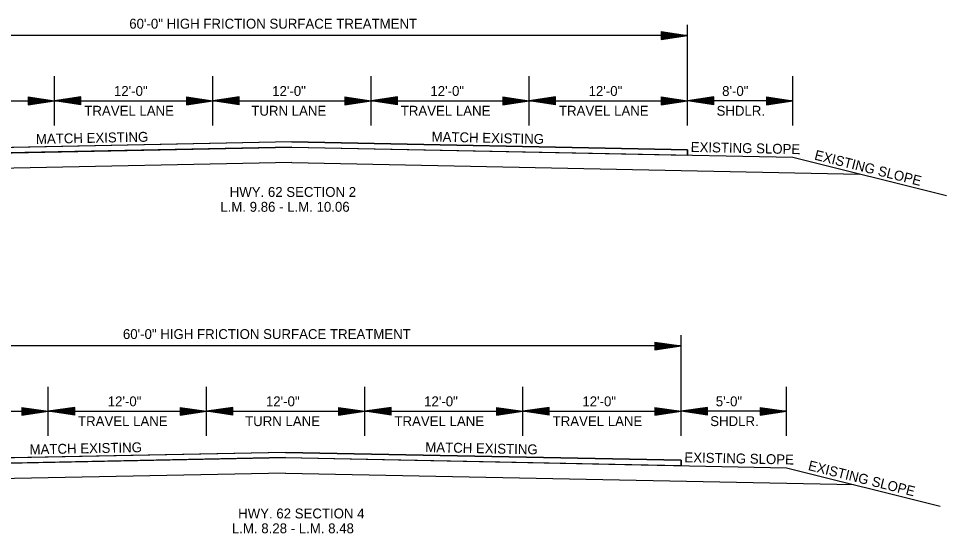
# Model space of a CAD drawing. Extents: x 34757 to 38214, y 51436 to 59430.
# Drawn here: x 37158 to 38214, y 53659 to 54244 of the extents above; entities that cross this region are included whole.
import ezdxf

# ---------------------------------------------------------------- set-up
doc = ezdxf.new("R2010")
doc.units = 0
for name, color, linetype in [('Default', 7, 'Continuous'), ('R_Border', 7, 'Continuous'), ('R_Draft', 7, 'Continuous')]:
    doc.layers.add(name, color=color, linetype=linetype)

msp = doc.modelspace()

# ---------------------------------------------------------------- linework, layer by layer
at = {"layer": 'Default'}
for p, q in [((37919.2, 54122.4), (37919.2, 54236.8)), ((37919.2, 54224.7), (37019.2, 54224.6)), ((37889.2, 54229.2), (37919.2, 54224.7)), ((37889.2, 54229.2), (37889.2, 54220.2)), ((37889.2, 54228.4), (37914.2, 54224.7)), ((37889.2, 54227.7), (37909, 54224.7)), ((37889.2, 54226.9), (37904, 54224.7)), ((37889.2, 54226.1), (37899, 54224.7)), ((37889.2, 54225.4), (37893.9, 54224.7)), ((37889.2, 54220.2), (37919.2, 54224.7)), ((37889.2, 54223.2), (37899, 54224.7)), ((37889.2, 54221.7), (37909, 54224.7)), ((37889.2, 54220.9), (37914.2, 54224.7)), ((37889.2, 54222.4), (37904, 54224.7)), ((37889.2, 54224), (37893.9, 54224.7)), ((37199.2, 54122.4), (37199.2, 54178.4)), ((37379.2, 54122.4), (37379.2, 54178.4)), ((37559.2, 54122.4), (37559.2, 54178.4)), ((37739.2, 54122.4), (37739.2, 54178.4)), ((37919.2, 54122.4), (37919.2, 54178.4)), ((38039.2, 54122.4), (38039.2, 54178.4)), ((37019.2, 54150.4), (37199.2, 54150.4)), ((37169.2, 54154.9), (37199.2, 54150.4)), ((37169.2, 54154.9), (37169.2, 54145.9)), ((37169.2, 54154.1), (37194.2, 54150.4)), ((37169.2, 54153.4), (37189, 54150.4)), ((37169.2, 54152.6), (37184, 54150.4)), ((37169.2, 54151.8), (37179, 54150.4)), ((37169.2, 54151.1), (37173.9, 54150.4)), ((37169.2, 54145.9), (37199.2, 54150.4)), ((37169.2, 54148.9), (37179, 54150.4)), ((37169.2, 54147.4), (37189, 54150.4)), ((37169.2, 54146.6), (37194.2, 54150.4)), ((37169.2, 54148.2), (37184, 54150.4)), ((37169.2, 54149.7), (37173.9, 54150.4)), ((37229.2, 54154.9), (37199.2, 54150.4)), ((37199.2, 54150.4), (37379.2, 54150.4)), ((37229.2, 54145.9), (37199.2, 54150.4)), ((37229.2, 54154.1), (37204.2, 54150.4)), ((37229.2, 54146.6), (37204.2, 54150.4)), ((37229.2, 54153.4), (37209.4, 54150.4)), ((37229.2, 54147.4), (37209.4, 54150.4)), ((37229.2, 54152.6), (37214.4, 54150.4)), ((37229.2, 54148.2), (37214.4, 54150.4)), ((37229.2, 54151.9), (37219.5, 54150.4)), ((37229.2, 54148.9), (37219.5, 54150.4)), ((37229.2, 54151.1), (37224.5, 54150.4)), ((37229.2, 54149.7), (37224.5, 54150.4)), ((37229.2, 54145.9), (37229.2, 54154.9)), ((37349.2, 54154.9), (37379.2, 54150.4)), ((37349.2, 54154.9), (37349.2, 54145.9)), ((37349.2, 54154.1), (37374.2, 54150.4)), ((37349.2, 54153.4), (37369, 54150.4)), ((37349.2, 54152.6), (37364, 54150.4)), ((37349.2, 54151.8), (37359, 54150.4)), ((37349.2, 54151.1), (37353.9, 54150.4)), ((37349.2, 54145.9), (37379.2, 54150.4)), ((37349.2, 54148.9), (37359, 54150.4)), ((37349.2, 54147.4), (37369, 54150.4)), ((37349.2, 54146.6), (37374.2, 54150.4)), ((37349.2, 54148.2), (37364, 54150.4)), ((37349.2, 54149.7), (37353.9, 54150.4)), ((37409.2, 54154.9), (37379.2, 54150.4)), ((37379.2, 54150.4), (37559.2, 54150.4)), ((37409.2, 54145.9), (37379.2, 54150.4)), ((37409.2, 54154.1), (37384.2, 54150.4)), ((37409.2, 54146.6), (37384.2, 54150.4)), ((37409.2, 54153.4), (37389.4, 54150.4)), ((37409.2, 54147.4), (37389.4, 54150.4)), ((37409.2, 54152.6), (37394.4, 54150.4)), ((37409.2, 54148.2), (37394.4, 54150.4)), ((37409.2, 54151.9), (37399.5, 54150.4)), ((37409.2, 54148.9), (37399.5, 54150.4)), ((37409.2, 54151.1), (37404.5, 54150.4)), ((37409.2, 54149.7), (37404.5, 54150.4)), ((37409.2, 54145.9), (37409.2, 54154.9)), ((37529.2, 54154.9), (37559.2, 54150.4)), ((37529.2, 54154.9), (37529.2, 54145.9)), ((37529.2, 54154.1), (37554.2, 54150.4)), ((37529.2, 54153.4), (37549, 54150.4)), ((37529.2, 54152.6), (37544, 54150.4)), ((37529.2, 54151.8), (37539, 54150.4)), ((37529.2, 54151.1), (37533.9, 54150.4)), ((37529.2, 54145.9), (37559.2, 54150.4)), ((37529.2, 54148.9), (37539, 54150.4)), ((37529.2, 54147.4), (37549, 54150.4)), ((37529.2, 54146.6), (37554.2, 54150.4)), ((37529.2, 54148.2), (37544, 54150.4)), ((37529.2, 54149.7), (37533.9, 54150.4)), ((37589.2, 54154.9), (37559.2, 54150.4)), ((37559.2, 54150.4), (37739.2, 54150.4)), ((37589.2, 54145.9), (37559.2, 54150.4)), ((37589.2, 54154.1), (37564.2, 54150.4)), ((37589.2, 54146.6), (37564.2, 54150.4)), ((37589.2, 54153.4), (37569.4, 54150.4)), ((37589.2, 54147.4), (37569.4, 54150.4)), ((37589.2, 54152.6), (37574.4, 54150.4)), ((37589.2, 54148.2), (37574.4, 54150.4)), ((37589.2, 54151.9), (37579.5, 54150.4)), ((37589.2, 54148.9), (37579.5, 54150.4)), ((37589.2, 54151.1), (37584.5, 54150.4)), ((37589.2, 54149.7), (37584.5, 54150.4)), ((37589.2, 54145.9), (37589.2, 54154.9)), ((37709.2, 54154.9), (37739.2, 54150.4)), ((37709.2, 54154.9), (37709.2, 54145.9)), ((37709.2, 54154.1), (37734.2, 54150.4)), ((37709.2, 54153.4), (37729, 54150.4)), ((37709.2, 54152.6), (37724, 54150.4)), ((37709.2, 54151.8), (37719, 54150.4)), ((37709.2, 54151.1), (37713.9, 54150.4)), ((37709.2, 54145.9), (37739.2, 54150.4)), ((37709.2, 54148.9), (37719, 54150.4)), ((37709.2, 54147.4), (37729, 54150.4)), ((37709.2, 54146.6), (37734.2, 54150.4)), ((37709.2, 54148.2), (37724, 54150.4)), ((37709.2, 54149.7), (37713.9, 54150.4)), ((37769.2, 54154.9), (37739.2, 54150.4)), ((37739.2, 54150.4), (37919.2, 54150.4)), ((37769.2, 54145.9), (37739.2, 54150.4)), ((37769.2, 54154.1), (37744.2, 54150.4)), ((37769.2, 54146.6), (37744.2, 54150.4)), ((37769.2, 54153.4), (37749.4, 54150.4)), ((37769.2, 54147.4), (37749.4, 54150.4)), ((37769.2, 54152.6), (37754.4, 54150.4)), ((37769.2, 54148.2), (37754.4, 54150.4)), ((37769.2, 54151.9), (37759.5, 54150.4)), ((37769.2, 54148.9), (37759.5, 54150.4)), ((37769.2, 54151.1), (37764.5, 54150.4)), ((37769.2, 54149.7), (37764.5, 54150.4)), ((37769.2, 54145.9), (37769.2, 54154.9)), ((37889.2, 54154.9), (37919.2, 54150.4)), ((37889.2, 54154.9), (37889.2, 54145.9)), ((37889.2, 54154.1), (37914.2, 54150.4)), ((37889.2, 54153.4), (37909, 54150.4)), ((37889.2, 54152.6), (37904, 54150.4)), ((37889.2, 54151.8), (37899, 54150.4)), ((37889.2, 54151.1), (37893.9, 54150.4)), ((37889.2, 54145.9), (37919.2, 54150.4)), ((37889.2, 54148.9), (37899, 54150.4)), ((37889.2, 54147.4), (37909, 54150.4)), ((37889.2, 54146.6), (37914.2, 54150.4)), ((37889.2, 54148.2), (37904, 54150.4)), ((37889.2, 54149.7), (37893.9, 54150.4)), ((37949.2, 54154.9), (37919.2, 54150.4)), ((38039.2, 54150.4), (37919.2, 54150.4)), ((37949.2, 54145.9), (37919.2, 54150.4)), ((37949.2, 54154.1), (37924.2, 54150.4)), ((37949.2, 54146.6), (37924.2, 54150.4)), ((37949.2, 54153.4), (37929.4, 54150.4)), ((37949.2, 54147.4), (37929.4, 54150.4)), ((37949.2, 54152.6), (37934.4, 54150.4)), ((37949.2, 54148.2), (37934.4, 54150.4)), ((37949.2, 54151.9), (37939.5, 54150.4)), ((37949.2, 54148.9), (37939.5, 54150.4)), ((37949.2, 54151.1), (37944.5, 54150.4)), ((37949.2, 54149.7), (37944.5, 54150.4)), ((37949.2, 54145.9), (37949.2, 54154.9)), ((38009.2, 54154.9), (38039.2, 54150.4)), ((38009.2, 54154.9), (38009.2, 54145.9)), ((38009.2, 54154.1), (38034.2, 54150.4)), ((38009.2, 54153.4), (38029, 54150.4)), ((38009.2, 54152.6), (38024, 54150.4)), ((38009.2, 54151.8), (38019, 54150.4)), ((38009.2, 54151.1), (38013.9, 54150.4)), ((38009.2, 54145.9), (38039.2, 54150.4)), ((38009.2, 54148.9), (38019, 54150.4)), ((38009.2, 54147.4), (38029, 54150.4)), ((38009.2, 54146.6), (38034.2, 54150.4)), ((38009.2, 54148.2), (38024, 54150.4)), ((38009.2, 54149.7), (38013.9, 54150.4)), ((37469.2, 54103.7), (37019.2, 54094.7)), ((37469.2, 54103.7), (37919.2, 54094.7)), ((38039.2, 54086.3), (38213.8, 54042.6)), ((37469.2, 54080.2), (36823.1, 54067.2)), ((37469.2, 54080.2), (38115.3, 54067.2)), ((37912, 53769.5), (37912, 53883.9)), ((37912, 53871.7), (37012, 53871.7)), ((37882, 53876.2), (37912, 53871.7)), ((37882, 53876.2), (37882, 53867.2)), ((37882, 53875.5), (37907, 53871.7)), ((37882, 53874.7), (37901.8, 53871.7)), ((37882, 53874), (37896.9, 53871.7)), ((37882, 53873.2), (37891.8, 53871.7)), ((37882, 53872.4), (37886.8, 53871.7)), ((37882, 53867.2), (37912, 53871.7)), ((37882, 53870.2), (37891.8, 53871.7)), ((37882, 53868.7), (37901.8, 53871.7)), ((37882, 53868), (37907, 53871.7)), ((37882, 53869.5), (37896.9, 53871.7)), ((37882, 53871), (37886.8, 53871.7)), ((37192, 53769.5), (37192, 53825.4)), ((37372, 53769.5), (37372, 53825.4)), ((37552, 53769.5), (37552, 53825.4)), ((37732, 53769.5), (37732, 53825.4)), ((37912, 53769.5), (37912, 53825.4)), ((38032, 53769.5), (38032, 53825.4)), ((37012, 53797.4), (37192, 53797.4)), ((37162, 53801.9), (37192, 53797.4)), ((37162, 53801.9), (37162, 53792.9)), ((37162, 53801.2), (37187, 53797.4)), ((37162, 53800.4), (37181.8, 53797.4)), ((37162, 53799.7), (37176.9, 53797.4)), ((37162, 53798.9), (37171.8, 53797.4)), ((37162, 53798.1), (37166.8, 53797.4)), ((37162, 53792.9), (37192, 53797.4)), ((37162, 53796), (37171.8, 53797.4)), ((37162, 53794.5), (37181.8, 53797.4)), ((37162, 53793.7), (37187, 53797.4)), ((37162, 53795.2), (37176.9, 53797.4)), ((37162, 53796.7), (37166.8, 53797.4)), ((37222, 53801.9), (37192, 53797.4)), ((37192, 53797.4), (37372, 53797.4)), ((37222, 53792.9), (37192, 53797.4)), ((37222, 53801.2), (37197, 53797.4)), ((37222, 53793.7), (37197, 53797.4)), ((37222, 53800.4), (37202.2, 53797.4)), ((37222, 53794.5), (37202.2, 53797.4)), ((37222, 53799.7), (37207.2, 53797.4)), ((37222, 53795.2), (37207.2, 53797.4)), ((37222, 53798.9), (37212.3, 53797.4)), ((37222, 53796), (37212.3, 53797.4)), ((37222, 53798.1), (37217.3, 53797.4)), ((37222, 53796.7), (37217.3, 53797.4)), ((37222, 53792.9), (37222, 53801.9)), ((37342, 53801.9), (37372, 53797.4)), ((37342, 53801.9), (37342, 53792.9)), ((37342, 53801.2), (37367, 53797.4)), ((37342, 53800.4), (37361.8, 53797.4)), ((37342, 53799.7), (37356.9, 53797.4)), ((37342, 53798.9), (37351.8, 53797.4)), ((37342, 53798.1), (37346.8, 53797.4)), ((37342, 53792.9), (37372, 53797.4)), ((37342, 53796), (37351.8, 53797.4)), ((37342, 53794.5), (37361.8, 53797.4)), ((37342, 53793.7), (37367, 53797.4)), ((37342, 53795.2), (37356.9, 53797.4)), ((37342, 53796.7), (37346.8, 53797.4)), ((37402, 53801.9), (37372, 53797.4)), ((37372, 53797.4), (37552, 53797.4)), ((37402, 53792.9), (37372, 53797.4)), ((37402, 53801.2), (37377, 53797.4)), ((37402, 53793.7), (37377, 53797.4)), ((37402, 53800.4), (37382.2, 53797.4)), ((37402, 53794.5), (37382.2, 53797.4)), ((37402, 53799.7), (37387.2, 53797.4)), ((37402, 53795.2), (37387.2, 53797.4)), ((37402, 53798.9), (37392.3, 53797.4)), ((37402, 53796), (37392.3, 53797.4)), ((37402, 53798.1), (37397.3, 53797.4)), ((37402, 53796.7), (37397.3, 53797.4)), ((37402, 53792.9), (37402, 53801.9)), ((37522, 53801.9), (37552, 53797.4)), ((37522, 53801.9), (37522, 53792.9)), ((37522, 53801.2), (37547, 53797.4)), ((37522, 53800.4), (37541.8, 53797.4)), ((37522, 53799.7), (37536.9, 53797.4)), ((37522, 53798.9), (37531.8, 53797.4)), ((37522, 53798.1), (37526.8, 53797.4)), ((37522, 53792.9), (37552, 53797.4)), ((37522, 53796), (37531.8, 53797.4)), ((37522, 53794.5), (37541.8, 53797.4)), ((37522, 53793.7), (37547, 53797.4)), ((37522, 53795.2), (37536.9, 53797.4)), ((37522, 53796.7), (37526.8, 53797.4)), ((37582, 53801.9), (37552, 53797.4)), ((37552, 53797.4), (37732, 53797.4)), ((37582, 53792.9), (37552, 53797.4)), ((37582, 53801.2), (37557, 53797.4)), ((37582, 53793.7), (37557, 53797.4)), ((37582, 53800.4), (37562.2, 53797.4)), ((37582, 53794.5), (37562.2, 53797.4)), ((37582, 53799.7), (37567.2, 53797.4)), ((37582, 53795.2), (37567.2, 53797.4)), ((37582, 53798.9), (37572.3, 53797.4)), ((37582, 53796), (37572.3, 53797.4)), ((37582, 53798.1), (37577.3, 53797.4)), ((37582, 53796.7), (37577.3, 53797.4)), ((37582, 53792.9), (37582, 53801.9)), ((37702, 53801.9), (37732, 53797.4)), ((37702, 53801.9), (37702, 53792.9)), ((37702, 53801.2), (37727, 53797.4)), ((37702, 53800.4), (37721.8, 53797.4)), ((37702, 53799.7), (37716.9, 53797.4)), ((37702, 53798.9), (37711.8, 53797.4)), ((37702, 53798.1), (37706.8, 53797.4)), ((37702, 53792.9), (37732, 53797.4)), ((37702, 53796), (37711.8, 53797.4)), ((37702, 53794.5), (37721.8, 53797.4)), ((37702, 53793.7), (37727, 53797.4)), ((37702, 53795.2), (37716.9, 53797.4)), ((37702, 53796.7), (37706.8, 53797.4)), ((37762, 53801.9), (37732, 53797.4)), ((37732, 53797.4), (37912, 53797.4)), ((37762, 53792.9), (37732, 53797.4)), ((37762, 53801.2), (37737, 53797.4)), ((37762, 53793.7), (37737, 53797.4)), ((37762, 53800.4), (37742.2, 53797.4)), ((37762, 53794.5), (37742.2, 53797.4)), ((37762, 53799.7), (37747.2, 53797.4)), ((37762, 53795.2), (37747.2, 53797.4)), ((37762, 53798.9), (37752.3, 53797.4)), ((37762, 53796), (37752.3, 53797.4)), ((37762, 53798.1), (37757.3, 53797.4)), ((37762, 53796.7), (37757.3, 53797.4)), ((37762, 53792.9), (37762, 53801.9)), ((37882, 53801.9), (37912, 53797.4)), ((37882, 53801.9), (37882, 53792.9)), ((37882, 53801.2), (37907, 53797.4)), ((37882, 53800.4), (37901.8, 53797.4)), ((37882, 53799.7), (37896.9, 53797.4)), ((37882, 53798.9), (37891.8, 53797.4)), ((37882, 53798.1), (37886.8, 53797.4)), ((37882, 53792.9), (37912, 53797.4)), ((37882, 53796), (37891.8, 53797.4)), ((37882, 53794.5), (37901.8, 53797.4)), ((37882, 53793.7), (37907, 53797.4)), ((37882, 53795.2), (37896.9, 53797.4)), ((37882, 53796.7), (37886.8, 53797.4)), ((37942, 53801.9), (37912, 53797.4)), ((38032, 53797.4), (37912, 53797.4)), ((37942, 53792.9), (37912, 53797.4)), ((37942, 53801.2), (37917, 53797.4)), ((37942, 53793.7), (37917, 53797.4)), ((37942, 53800.4), (37922.2, 53797.4)), ((37942, 53794.5), (37922.2, 53797.4)), ((37942, 53799.7), (37927.2, 53797.4)), ((37942, 53795.2), (37927.2, 53797.4)), ((37942, 53798.9), (37932.3, 53797.4)), ((37942, 53796), (37932.3, 53797.4)), ((37942, 53798.1), (37937.3, 53797.4)), ((37942, 53796.7), (37937.3, 53797.4)), ((37942, 53792.9), (37942, 53801.9)), ((38002, 53801.9), (38032, 53797.4)), ((38002, 53801.9), (38002, 53792.9)), ((38002, 53801.2), (38027, 53797.4)), ((38002, 53800.4), (38021.8, 53797.4)), ((38002, 53799.7), (38016.9, 53797.4)), ((38002, 53798.9), (38011.8, 53797.4)), ((38002, 53798.1), (38006.8, 53797.4)), ((38002, 53792.9), (38032, 53797.4)), ((38002, 53796), (38011.8, 53797.4)), ((38002, 53794.5), (38021.8, 53797.4)), ((38002, 53793.7), (38027, 53797.4)), ((38002, 53795.2), (38016.9, 53797.4)), ((38002, 53796.7), (38006.8, 53797.4)), ((37462, 53750.7), (37012, 53741.7)), ((37462, 53750.7), (37912, 53741.7)), ((37462, 53727.2), (36815.9, 53714.3)), ((37462, 53727.2), (38108.1, 53714.3)), ((38032, 53733.3), (38206.6, 53689.6))]:
    msp.add_line(p, q, dxfattribs=at)
for points in [[(37019.2, 54094.7), (37019.2, 54088.7), (37469.2, 54097.7), (37919.2, 54088.7), (37919.2, 54094.7), (37469.2, 54103.7)], [(37012, 53741.7), (37012, 53735.7), (37462, 53744.7), (37912, 53735.7), (37912, 53741.7), (37462, 53750.7)]]:
    msp.add_lwpolyline(points, close=True, dxfattribs=at)
for points in [[(37469.2, 54097.7), (36899.2, 54086.3)], [(37469.2, 54097.7), (38039.2, 54086.3)], [(37462, 53744.7), (36892, 53733.3)], [(37462, 53744.7), (38032, 53733.3)]]:
    msp.add_lwpolyline(points, dxfattribs=at)
at = {"layer": 'R_Draft'}
for p, q in [((37919.2, 54094.7), (37919.2, 54088.7)), ((37912, 53741.7), (37912, 53735.7))]:
    msp.add_line(p, q, dxfattribs=at)

# ---------------------------------------------------------------- texts
at = {"layer": 'Default'}
for s, p in [('60\'-0" HIGH FRICTION SURFACE TREATMENT', (37284.1, 54232.5)), ('12\'-0"', (37266.7, 54156)), ('12\'-0"', (37446.7, 54156)), ('12\'-0"', (37626.7, 54156)), ('12\'-0"', (37806.7, 54156)), ('8\'-0"', (37958.6, 54156)), ('TRAVEL LANE', (37233, 54133.5)), ('TURN LANE', (37423, 54133.5)), ('TRAVEL LANE', (37593, 54133.5)), ('TRAVEL LANE', (37773, 54133.5)), ('SHDLR.', (37952.3, 54133.5)), ('60\'-0" HIGH FRICTION SURFACE TREATMENT', (37276.9, 53879.6)), ('12\'-0"', (37259.6, 53803.1)), ('12\'-0"', (37439.6, 53803.1)), ('12\'-0"', (37619.6, 53803.1)), ('12\'-0"', (37799.6, 53803.1)), ('5\'-0"', (37951.4, 53803.1)), ('TRAVEL LANE', (37225.8, 53780.6)), ('TURN LANE', (37415.9, 53780.6)), ('TRAVEL LANE', (37585.8, 53780.6)), ('TRAVEL LANE', (37765.8, 53780.6)), ('SHDLR.', (37945.1, 53780.6))]:
    msp.add_text(s, height=11.25, dxfattribs=at).set_placement(p)
for s, rotation, p in [('MATCH EXISTING', 1.146, (37178, 54101.4)), ('MATCH EXISTING', 358.7756, (37628, 54104.1)), ('EXISTING SLOPE', 358.7756, (37922.8, 54092.4)), ('EXISTING SLOPE', 345.9632, (38062.9, 54083.8)), ('MATCH EXISTING', 1.146, (37170.8, 53748.4)), ('MATCH EXISTING', 358.7756, (37620.8, 53751.1)), ('EXISTING SLOPE', 358.7756, (37915.6, 53739.5)), ('EXISTING SLOPE', 345.9632, (38055.7, 53730.8))]:
    msp.add_text(s, height=11.25, rotation=rotation, dxfattribs=at).set_placement(p)
at = {"layer": 'R_Border'}
for s, p in [('HWY. 62 SECTION 2', (37398.4, 54041.2)), ('L.M. 9.86 - L.M. 10.06', (37387.7, 54024.3)), ('HWY. 62 SECTION 4', (37408, 53675.6)), ('L.M. 8.28 - L.M. 8.48', (37400.9, 53658.7))]:
    msp.add_text(s, height=11.25, dxfattribs=at).set_placement(p)

doc.saveas('drawing.dxf')
